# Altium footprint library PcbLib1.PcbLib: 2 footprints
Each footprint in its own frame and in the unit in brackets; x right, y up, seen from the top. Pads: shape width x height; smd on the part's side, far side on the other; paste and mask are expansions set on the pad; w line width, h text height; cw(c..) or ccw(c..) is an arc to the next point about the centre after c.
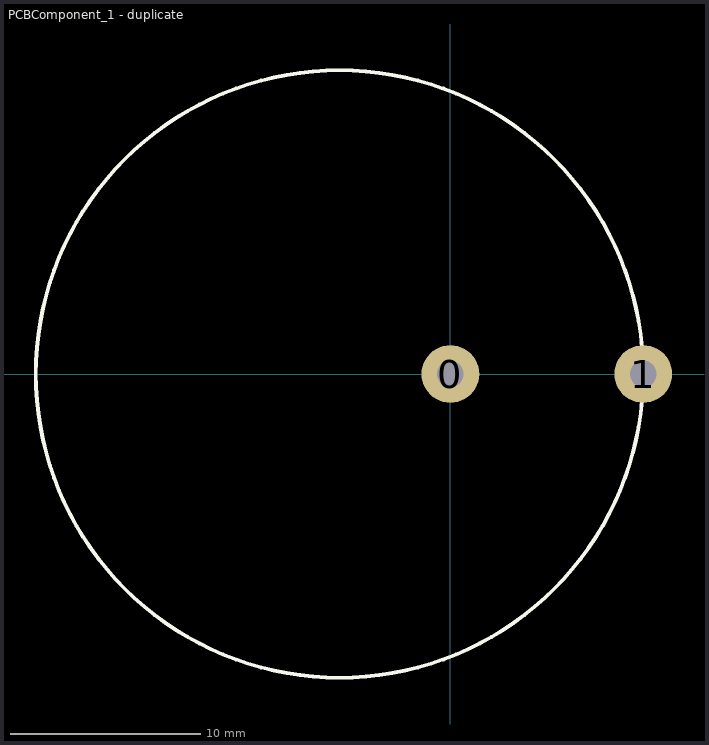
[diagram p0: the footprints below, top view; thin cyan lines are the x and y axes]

## PCBComponent_1 [mil]

## PCBComponent_1 - duplicate [mil]
pads (2):
  round 120 hole 55: 0(0,0) 1(400,0)
Top Overlay:
  circle w7.87: c-230,0 r630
